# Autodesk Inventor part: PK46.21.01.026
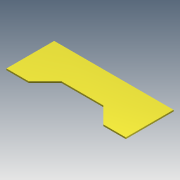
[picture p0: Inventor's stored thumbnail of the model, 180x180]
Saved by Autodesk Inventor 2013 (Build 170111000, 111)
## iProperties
Created: 2005-04
Part Number: PK46.21.01.026
Material: Steel, Mild
Document SubType Name: Modeling
Designer: salex
Manufacturer: Standard
Standards Organization: Custom
Density: 7.86 g/cm^3
Author: salex
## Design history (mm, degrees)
sketch "Эскиз1"
  geometry: L1 (0, 0)-(0, 320); L2 (0, 320)-(800, 320); L3 (800, 320)-(800, 0); L4 (800, 0)-(650, 0); L5 (650, 0)-(540, 110); L6 (540, 110)-(260, 110); L7 (260, 110)-(150, 0); L8 (150, 0)-(0, 0)
  constraints: 16 end point, 4 parallel, 3 equal length, 1 perpendicular, 1 vertical, 1 other
  dimensions: "d0" = 800 distance of L1.end L2.end; "d1" = 110 distance between parallel lines of L6 L8; "d2" = 320 distance of L1.start L1.end; "d3" = 150 distance of L7.end L1.start; "d4" = 260 distance from line of L6.end L1
extrude "Выдавливание1" new body sketch "Эскиз1" distance "d5" = 10; taper "d6" = 0 deg
body "Solid1"
